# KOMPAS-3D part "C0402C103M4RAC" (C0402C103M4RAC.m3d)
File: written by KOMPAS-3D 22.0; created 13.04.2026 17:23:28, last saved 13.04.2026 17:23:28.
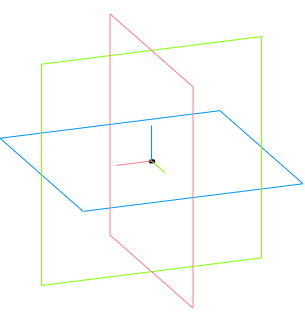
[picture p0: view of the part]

Document properties: Автор: Andrey; Полное имя файла: C:\Users\User1\Documents\C0402C103M4RAC.m3d

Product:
- Part/product: C0402C103M4RAC

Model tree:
1. Операция без истории:1
2. Операция без истории:2
3. Операция без истории:3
